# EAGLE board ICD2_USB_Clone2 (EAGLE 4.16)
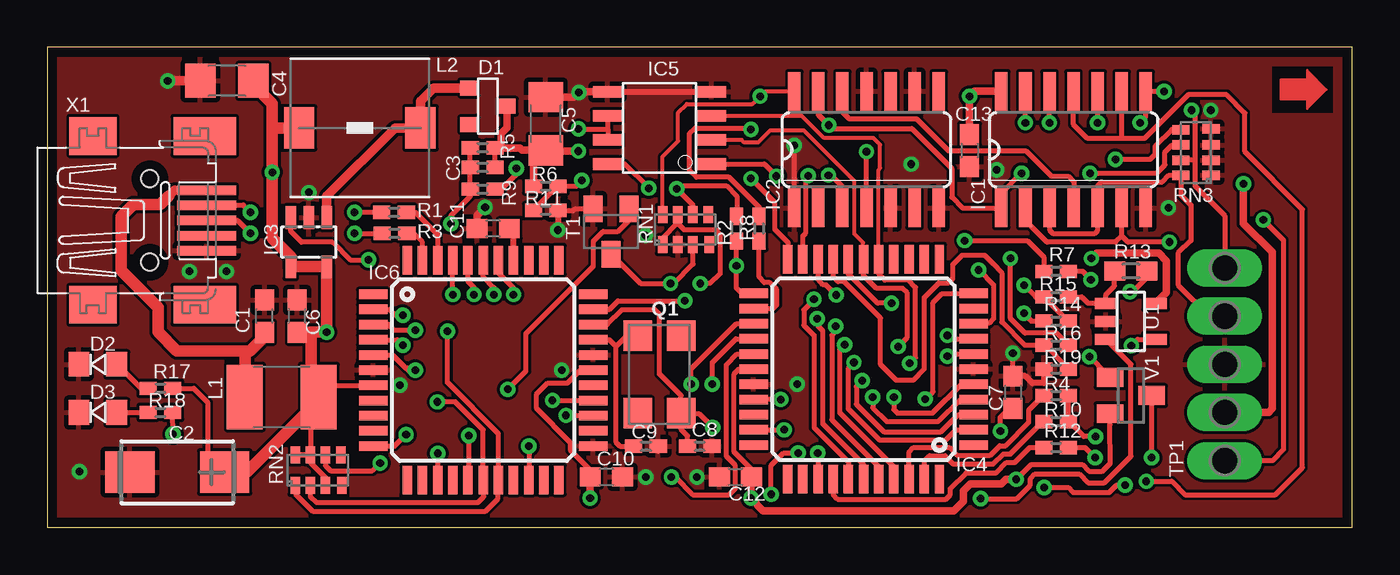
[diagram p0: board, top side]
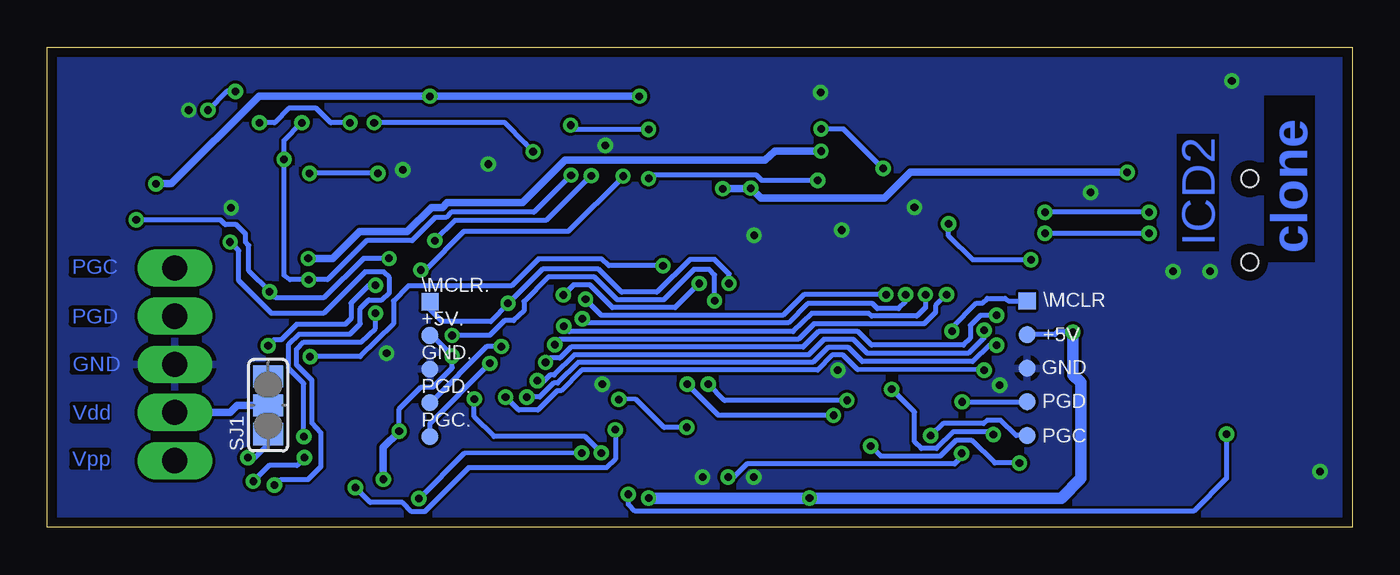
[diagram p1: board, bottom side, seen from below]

Size 68.81 x 25.32 mm. Coordinates in mm from the lower left corner, seen from the top.
Outline: 0,0 68.81,0 68.81,25.32 0,25.32 0,0
Copper layers (1*16): Top 0.035mm / dielectric 1.5mm / Bottom 0.035mm
Design rules "gt_001": minimum track width 6mil, minimum drill 12mil, track to track 6mil, track to pad 6mil, pad to pad 8mil, via to via 8mil, smd to smd 8mil, copper to edge 20mil, drill to drill 8mil, minimum pad ring 10mil, minimum via ring 8mil, stop-mask expansion 4mil, vias tented up to drill 0mil, thermal gap 10mil
tRestrict: area 64.6,21.9 to 67.8,24.3
bRestrict: area 7,14.6 to 9.2,20.7; area 2,14 to 4.6,22.8

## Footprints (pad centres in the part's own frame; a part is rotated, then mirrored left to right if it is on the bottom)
TP09R = smd 0.9 x 0.9: TP 0,0
TP09SQ = smd 0.9 x 0.9: TP 0,0
C0603 = smd 1.1 x 1: 1 -0.85,0; 2 0.85,0
CT6032 = smd 2.6 x 2.2: + 2.5,0; - -2.5,0
C0402 = smd 0.9 x 0.7: 1 -0.65,0; 2 0.65,0
C1206 = smd 1.6 x 1.8: 1 -1.4,0; 2 1.4,0
SOD23 = smd 0.787 x 0.889: 1 -0.94,-0.254; 2 0.991,-0.254; 3 0.025,-2.286
LED0805 = smd 1.1 x 1.3: A -1,0; K 1,0
SO14 = smd 0.66 x 2.032: 1 -3.81,-3.073; 2 -2.54,-3.073; 3 -1.27,-3.073; 4 0,-3.073; 5 1.27,-3.073; 6 2.54,-3.073; 7 3.81,-3.073; 8 3.81,3.073; 9 2.54,3.073; 10 1.27,3.073; 11 0,3.073; 12 -1.27,3.073; 13 -2.54,3.073; 14 -3.81,3.073
SOT23-5 = smd 0.55 x 1.2: 1 -0.95,-1.3; 2 0,-1.3; 3 0.95,-1.3; 4 0.95,1.3; 5 -0.95,1.3
TQFP44 = smd 1.5 x 0.5: 1 -5.8,4; 2 -5.8,3.2; 3 -5.8,2.4; 4 -5.8,1.6; 5 -5.8,0.8; 6 -5.8,0; 7 -5.8,-0.8; 8 -5.8,-1.6; 9 -5.8,-2.4; 10 -5.8,-3.2; 11 -5.8,-4; 23 5.8,-4; 24 5.8,-3.2; 25 5.8,-2.4; 26 5.8,-1.6; 27 5.8,-0.8; 28 5.8,0; 29 5.8,0.8; 30 5.8,1.6; 31 5.8,2.4; 32 5.8,3.2; 33 5.8,4 | smd 0.5 x 1.5: 12 -4,-5.8; 13 -3.2,-5.8; 14 -2.4,-5.8; 15 -1.6,-5.8; 16 -0.8,-5.8; 17 0,-5.8; 18 0.8,-5.8; 19 1.6,-5.8; 20 2.4,-5.8; 21 3.2,-5.8; 22 4,-5.8; 34 4,5.8; 35 3.2,5.8; 36 2.4,5.8; 37 1.6,5.8; 38 0.8,5.8; 39 0,5.8; 40 -0.8,5.8; 41 -1.6,5.8; 42 -2.4,5.8; 43 -3.2,5.8; 44 -4,5.8
SO8 = smd 0.61 x 1.524: 1 -1.27,-2.743; 2 0,-2.743; 3 1.27,-2.743; 4 2.54,-2.743; 5 2.54,2.743; 6 1.27,2.743; 7 0,2.743; 8 -1.27,2.743
L1812 = smd 1.9 x 3.4: 1 -1.95,0; 2 1.95,0
WE-PD_S/M = smd 1.6 x 2.2: 1 -3.2,0; 2 3.2,0
HCX5SB = smd 1.6 x 1.5: 1 -2.05,-1.15; 2 2.05,-1.15; 3 2.05,1.15; 4 -2.05,1.15
R0402 = smd 0.9 x 0.7: 1 -0.65,0; 2 0.65,0
R0603 = smd 1.1 x 1: 1 -0.85,0; 2 0.85,0
CTS-742*083 = smd 0.5 x 0.9: 1 -1.2,-0.8; 2 -0.4,-0.8; 3 0.4,-0.8; 4 1.25,-0.8; 5 1.2,0.8; 6 0.4,0.8; 7 -0.4,0.8; 8 -1.2,0.8
SJ_2 = smd 1.168 x 1.6: 1 -1.524,0; 2 0,0; 3 1.524,0
SC59-BEC = smd 1 x 1.4: B -0.95,-1.2; C 0,1.2; E 0.95,-1.2
P5-25-13 = drill 1.321 pad 1.905 long: 1 -5.08,0; 2 -2.54,0; 3 0,0; 4 2.54,0; 5 5.08,0
SOT23-5' = smd 0.6 x 1.2: 1 -0.95,-1.306; 2 0,-1.306; 3 0.95,-1.306; 4 0.95,1.306; 5 -0.95,1.306
SOT23 = smd 1 x 1.4: 1 -0.95,-1.1; 2 0.95,-1.1; 3 0,1.1
32005-201 = smd 3.1 x 0.5: 1 3,1.6; 2 3,0.8; 3 3,0; 4 3,-0.8; 5 3,-1.6 | smd 2.5 x 2: M1 -3,-4.45; M2 -3,4.45 | smd 3.3 x 2: M3 2.9,4.45; M4 2.9,-4.45 | hole 0.9: 0,2.2; 0,-2.2

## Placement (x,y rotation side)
+5V  TPSQTP09R  [TP09R]  17.14,10.17 270 bottom
+5V.  TPSQTP09R  [TP09R]  48.64,10.12 0 bottom
\MCLR  TPSQTP09SQ  [TP09SQ]  17.14,11.95 270 bottom
\MCLR.  TPSQTP09SQ  [TP09SQ]  48.64,11.9 0 bottom
C1  100n  [C0603]  11.45,11.14 90 top
C2  10u/20V  [CT6032]  6.85,2.91 0 top
C3  220p  [C0402]  22.96,18.99 180 top
C4  1u  [C1206]  9.47,23.56 180 top
C5  4u7/20V  [C1206]  26.28,21.3 90 top
C6  100n  [C0603]  13.18,11.14 90 top
C7  100n  [C0603]  50.92,7.12 270 top
C8  22p  [C0402]  34.41,4.28 0 top
C9  22p  [C0402]  31.57,4.28 0 top
C10  100n  [C0603]  29.48,2.65 180 top
C11  220n  [C0603]  23.52,15.76 180 top
C12  100n  [C0603]  36.29,2.65 0 top
C13  100n  [C0603]  48.64,19.88 270 top
D1  BAT54C  [SOD23]  21.97,22.19 90 top
D2  gn  [LED0805]  2.66,8.6 180 top
D3  rt  [LED0805]  2.66,6.06 180 top
GND  TPSQTP09R  [TP09R]  17.14,8.39 270 bottom
GND.  TPSQTP09R  [TP09R]  48.64,8.34 0 bottom
IC1  74HC126D  [SO14]  54.12,19.93 0 top
IC2  74HC14D  [SO14]  43.2,19.93 0 top
IC3  LM2704  [SOT23-5]  13.79,15.05 180 top
IC4  PIC16F877A-20/PT  [TQFP44]  43.05,8.34 180 top
IC5  MCP41010  [SO8]  32.28,20.43 90 top
IC6  PIC18F4550-I/PT  [TQFP44]  22.98,8.29 0 top
L1  10uH  [L1812]  12.36,6.87 180 top
L2  10uH  [WE-PD_S/M]  16.48,21.07 180 top
PGC  TPSQTP09R  [TP09R]  17.14,4.84 270 bottom
PGC.  TPSQTP09R  [TP09R]  48.64,4.79 0 bottom
PGD  TPSQTP09R  [TP09R]  17.14,6.62 270 bottom
PGD.  TPSQTP09R  [TP09R]  48.64,6.57 0 bottom
Q1  20.00MHz  [HCX5SB]  32.28,8.06 90 top
R1  27R  [R0402]  18.28,16.62 0 top
R2  10k  [R0402]  36.34,15.76 90 top
R3  27R  [R0402]  18.31,15.51 0 top
R4  330R  [R0402]  53.21,6.95 0 top
R5  100k  [R0402]  22.96,20.03 0 top
R6  15k  [R0402]  26.28,18 180 top
R7  1k  [R0402]  53.21,13.5 0 top
R8  1k  [R0402]  37.54,15.76 90 top
R9  4k7  [R0402]  22.96,17.84 180 top
R10  330R  [R0402]  53.21,5.58 0 top
R11  4k7  [R0402]  26.28,16.73 180 top
R12  330R  [R0402]  53.21,4.2 0 top
R13  56R  [R0603]  57.14,13.53 0 top
R14  4k70  [R0402]  53.21,10.88 0 top
R15  13k0  [R0402]  53.21,12.15 180 top
R16  15k  [R0402]  53.21,9.61 0 top
R17  510R  [R0402]  5.96,7.33 0 top
R18  510R  [R0402]  5.96,6.06 0 top
R19  4k7  [R0402]  53.21,8.34 0 top
RN1  10k  [CTS-742*083]  33.65,15.71 0 top
RN2  10k  [CTS-742*083]  14.27,3.01 0 top
RN3  10k  [CTS-742*083]  60.57,19.77 90 top
SJ1  [SJ_2]  57.17,6.44 90 bottom
T1  RN1402  [SC59-BEC]  29.74,15.61 180 top
TP1  TP5P5-25-13  [P5-25-13]  62.1,8.6 90 top
U1  LM7301  [SOT23-5']  57.14,10.86 270 top
U$1  [ARROW]  66.7,23.1 0 top
V1  BSS84  [SOT23]  57.14,6.95 270 top
X1  MINI-USB-SCHIELD-32005-201  [32005-201]  5.41,16.19 0 top

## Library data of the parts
+5V +5V. \MCLR \MCLR. GND GND. PGC PGC. PGD PGD. TP1 = testpad
C1-C13 L1 R1-R19 RN1-RN3 = rcl
D1 = CONTR@3
D2 D3 = CONTR1
IC1 IC2 = 74xx-eu
IC3 = national
IC4 IC6 = microchip
IC5 = MICROCH
L2 = wuerth-elektronik
Q1 = crystal
SJ1 = jumper
T1 = transistor
U1 = linear
U$1 = special_las
V1 = transistor-fet
X1 = con-cypressindustries

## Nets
+5V: +5V..TP +5V.TP C2.+ C4.1 C6.1 C7.2 C10.2 C12.2 IC3.4 IC3.5 IC4.7 IC4.28 IC5.8 IC6.7 IC6.28 L1.1 L2.2 R2.2 R17.2 RN1.6 RN2.3 RN2.7 RN2.8 V1.2
+5V_EXT: SJ1.3
+15V: C3.1 C5.1 D1.3 R5.2 R6.2 U1.5
\CS: IC4.9 IC5.1
ACT: IC4.11 R18.2
BUSY: IC4.8 IC6.32
CS: IC4.27 IC6.14
GND: C1.2 C2.- C4.2 C5.2 C6.2 C7.1 C8.2 C9.2 C10.1 C11.2 C12.1 C13.2 D2.K D3.K GND..TP GND.TP IC1.7 IC2.1 IC2.5 IC2.7 IC2.9 IC2.11 IC3.2 IC4.6 IC4.29 IC5.4 IC5.5 IC6.6 IC6.23 IC6.29 R11.1 R19.1 RN1.2 RN3.1 RN3.2 RN3.3 RN3.4 T1.E TP1.3 U1.2 X1.5
N$1: C1.1 L1.2 X1.1
N$2: C11.1 IC6.37
N$3: D1.2 IC3.1 L2.1
N$4: C9.1 IC6.30 Q1.3
N$5: C3.2 IC3.3 R5.1 R9.2
N$6: C8.1 IC4.30 IC6.31 Q1.1
N$7: IC5.6 IC5.7 R9.1
N$8: IC1.2 IC1.6 R4.2 R10.2
N$9: IC6.16 PGC.TP
N$10: IC6.17 PGD.TP RN2.2
N$11: \MCLR.TP IC6.18 RN2.1
N$12: D2.A R17.1
N$13: R3.1 X1.3
N$14: R1.1 X1.2
N$15: IC1.1 IC2.13 R8.2 RN3.6
N$16: IC4.23 R2.1 V1.1
N$17: IC1.4 IC2.12
N$18: \MCLR..TP IC4.18 RN1.3 T1.C
N$19: IC6.20 RN2.6
N$20: D3.A R18.1
N$21: IC4.22 R6.1 R11.2
N$22: IC1.9 IC1.11 R12.2
N$23: IC1.3 IC1.5 RN3.8 TP1.4
N$26: IC6.11 T1.B
N$27: IC4.20 RN1.1 RN1.7
N$28: R13.1 R15.1 U1.1
N$29: IC4.37 R12.1
N$30: IC1.8 IC1.12 RN3.7 TP1.5
N$32: IC4.42 R4.1
N$33: IC4.43 R10.1
N$34: IC4.19 R16.1 R19.2
N$35: R13.2 R16.2 TP1.1
N$36: R14.2 R15.2 U1.4
N$37: SJ1.1 V1.3
N$39: IC4.36 U1.3
N$40: IC4.32 R14.1
N$41: IC1.13 IC2.4
N$42: IC1.10 IC2.3 R7.2 RN3.5
N$43: IC4.24 R8.1
N$45: IC4.21 R7.1
PD.0: IC4.38 IC6.38
PD.1: IC4.39 IC6.39
PD.2: IC4.40 IC6.40
PD.3: IC4.41 IC6.41
PD.4: IC4.2 IC6.2
PD.5: IC4.3 IC6.3
PD.6: IC4.4 IC6.4
PD.7: IC4.5 IC6.5
RD: IC4.25 IC6.26
SCK: IC4.17 IC5.2 PGD..TP
SI: IC4.16 IC5.3 PGC..TP
T_VDD: C13.1 IC1.14 IC2.14 RN1.8 SJ1.2 TP1.2
USB_+IN: IC6.43 R3.2
USB_-IN: IC6.42 R1.2
WR: IC4.26 IC6.25

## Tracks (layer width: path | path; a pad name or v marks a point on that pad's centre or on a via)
+5V  (via drill 0.4)
  Top 0.152: IC3.4 12.85,13.75
  Top 0.254: RN2.8 13.49,3.81 | IC4.28 36.47,8.34 36.21,8.09 36.21,3.98 37.1,3.09 | C12.2 37.13,2.65 37.13,3.06 37.1,3.09 | IC5.8 30.45,19.16 v31.72,17.89 | R2.2 36.34,16.4 36.37,16.37 36.37,17.46 35.81,18.02 33.34,18.02 v33.19,17.87 34.05,17.01 34.03,17.01 34.05,16.99 RN1.6 | C10.2 28.63,2.71 28.62,2.73 28.62,3.01 | 37.1,2.27 37.1,3.09 | v51.1,2.53 51.89,3.31 54.58,3.31 54.93,2.96 55.65,2.96 56.05,3.37 56.04,5.41 V1.2 | IC6.28 28.11,8.29 27.43,7.61 26.39,7.61 25.8,7.05 25.8,6.26 27.61,4.46 27.61,4.05 28.65,3.01 28.62,3.01 | 28.62,2.5 28.62,3.01 | 28.62,2.43 28.62,3.01 | 28.62,3.01 28.62,3.04 | RN2.7 RN2.8 | RN2.7 13.55,3.81 | IC4.7 47.58,9.14 v47.47,9.03 | C7.2 50.73,6.27 50.26,5.8 v50.26,5.07 | R17.2 7.72,7.33 8.45,6.59 8.45,3.7 9.34,2.91 | 13,3.85 13.05,3.81 RN2.8 | RN2.7 13.87,3.41 13.89,3.39 | RN2.3 14.67,2.35 14.68,2.35 14.68,2.6 13.89,3.39 | 13.9,6.3 13.9,6.31 13.89,6.31 13.89,3.39 | 13.91,7.56 13.99,7.51 14,7.49 IC6.7
  Top 0.406: 37.1,2.27 v37.1,1.54 37.74,0.88 47.82,0.88 48.31,1.36 48.31,1.92 48.69,2.3 50.31,2.3 50.54,2.53 v51.1,2.53 | 28.62,2.5 28.62,2.43 v28.62,1.54
  Top 0.61: C2.+ 9.34,2.91 10.51,2.91 13.9,6.3 13.94,6.39 13.94,6.87 L1.1 13.91,7.56 13.91,10.29 | v14.73,10.3 13.91,10.27 | C6.1 13.9,10.29 13.91,10.29 | 13.91,10.29 v14.73,10.3 | IC3.5 | IC3.5 12.85,13.75 12.85,14.26 11.86,15.25 v11.86,18.73 11.86,21.07 | v14.73,10.3 IC3.5 | 11.86,21.07 L2.2 | C4.1 10.87,23.35 11.86,22.36 11.86,21.07
  Bottom 0.254: v31.72,17.89 31.75,17.87 | v14.73,10.3 15.54,10.3 15.67,10.17 +5V.TP | +5V..TP 48.53,10.12 47.47,9.06 v47.47,9.03 47.44,9.03 47.47,9 47.47,8.42 48.48,7.4 49.09,7.4 50.26,6.24 v50.26,5.07
  Bottom 0.406: 31.75,17.87 v33.19,17.87 | v11.86,18.73 23.29,18.73 24.66,17.36 31.19,17.36 v31.72,17.89 | v50.26,5.07 50.26,5.04 51.1,4.2 v51.1,2.53
  Bottom 0.61: v14.73,10.3 14.73,8.04 14.29,7.63 14.29,2.58 15.34,1.54 v28.62,1.54 v37.1,1.54
+15V  (via drill 0.4)
  Top 0.254: C3.1 R5.2 23.62,20.03
  Top 0.305: 23.62,20.03 23.92,20.03 | 26.26,19.85 C5.1 | 23.97,20 23.97,20.03 23.62,20.03 | 23.62,20.03 R5.2
  Top 0.406: D1.3 24.25,21.09 23.92,20.76 23.92,20.03 | R6.2 25.63,19.23 26.26,19.85 | C5.1 25.04,19.9 24.94,20 23.97,20 | C5.1 27.28,19.85 v28.01,19.85 | v55.06,14.19 55.34,14.47 58.62,14.47 59.02,14.06 59.02,12.38 58.44,11.8 58.44,11.81 U1.5
  Bottom 0.406: v28.01,19.85 30.45,19.85 30.96,19.37 41.52,19.37 43.76,17.13 47.72,17.13 47.98,16.88 48.56,16.88 49.83,15.61 52.34,15.61 53.77,14.19 v55.06,14.19
\CS  (via drill 0.4)
  Top 0.254: IC5.1 37.82,19.16 v38.45,18.53 | v49.12,13.58 49.91,12.79 49.91,11.01 49.65,10.76 48.91,10.76 48.89,10.74 IC4.9
  Bottom 0.254: v38.45,18.53 38.45,18.48 41.35,15.61 46.86,15.61 48.86,13.58 v49.12,13.58
ACT  (via drill 0.4)
  Top 0.254: v38.17,1.74 38.17,3.26 38.83,3.92 v39.59,3.92 | v46.3,6.77 46.71,7.15 46.71,11.85 47.19,12.33 48.81,12.33 48.81,12.34 IC4.11 | v6.62,4.92 R18.2
  Bottom 0.254: v6.62,4.92 6.62,2.58 8.35,0.85 37.82,0.85 38.17,1.21 v38.17,1.74 | v39.59,3.92 40.46,4.79 45.26,4.79 46.3,5.83 v46.3,6.77
BUSY  (via drill 0.4)
  Top 0.254: IC6.32 29.59,11.49 29.64,11.49 30.09,11.95 v33.62,11.95 | 48.81,9.94 | 48.81,9.94 IC4.8 | v47.47,10.12 47.64,9.94 48.81,9.94
  Bottom 0.254: v47.47,10.12 45.49,10.12 44.7,10.91 44.22,10.91 43.68,11.42 43.68,11.93 42.41,13.2 39.95,13.2 38.75,12 36.32,12 34.72,13.6 33.9,13.6 33.62,13.32 v33.62,11.95
CS  (via drill 0.4)
  Top 0.254: IC4.27 36.38,9.14 35.81,8.57 35.81,3.75 36.29,3.26 36.29,2.04 35.96,1.71 34.03,1.71 33.09,2.65 v32.91,2.65 | IC6.14 20.58,2.55 20.59,2.55 v20.59,3.9
  Bottom 0.254: v32.91,2.65 32.61,2.65 31.92,3.34 20.98,3.34 20.59,3.72 v20.59,3.9
GND  (via drill 0.4)
  Top 0.152: C1.2 11.48,12 C1.2
  Top 0.254: T1.E 27.84,16.81 27.73,16.7 26.93,16.7 | 26.93,16.7 26.92,16.7 | R11.1 26.93,16.7 | IC2.1 v39.39,20.16 | RN3.2 61.37,19.42 61.36,19.42 61.37,19.41 | RN3.4 61.37,21.04 61.39,21.07 61.37,21.06 | C10.1 30.32,2.65 | IC6.23 28.78,4.2 | v39.54,7.56 39.53,7.54 | 50.95,7.96 50.95,7.97 C7.1 | C7.1 v50.92,9.18 | C7.1 50.92,7.96 | C9.2 32.22,4.25 32.23,4.25 32.23,4 | RN3.3 61.39,20.21 61.37,20.19 RN3.3
  Top 0.305: R11.1 26.93,15.7 v26.92,15.68 | IC5.5 29.54,23 29.56,22.95 29.59,22.97 IC5.4 | 50.95,7.97 51.57,7.97 51.94,7.61 52.55,7.61 52.55,8.22 52.57,8.24 52.56,8.27 R19.1
  Top 0.406: C11.2 22.67,16.46 v23.08,16.88 | C5.2 27.79,22.7 v28.04,22.95 28.06,22.97 IC5.5 | D3.K
  Top 0.508: v6.34,23.56 C4.2
  Top 0.61: C1.2
  other vias: 13.79,17.67 18.59,7.51 1.7,2.93 9.44,13.5 45.56,19.16 50.06,18.86 31.54,15.41 61.36,22.01 59.13,16.85 31.57,2.65 34.26,2.65 27.12,8.29 7.49,13.5
  pour Bottom: 0.25,25.08 68.58,25.08 68.58,0.24 0.2,0.24 0.2,25.03
  pour Top: 0.25,25.01 68.58,25.01 68.58,0.29 0.25,0.29
N$1
  Top 0.406: X1.1 | X1.1 | 6.7,17.79 X1.1 | X1.1
  Top 0.508: 6.4,17.49 6.7,17.79
  Top 0.61: 6.4,17.49 5.94,17.03 4.52,17.03 3.88,16.4 3.88,13.55 5.84,11.6 5.84,10.3 6.83,9.31 10.43,9.31 | C1.1 11.45,10.07 10.69,9.31 10.43,9.31 | L1.2 10.44,9.3 10.43,9.31
N$2
  Top 0.305: C11.1 24.37,15.66 24.35,15.66 24.58,15.43 IC6.37
N$3
  Top 0.508: IC3.1 14.74,17.47 18.33,21.07 L2.1 | L2.1 | L2.1 19.68,21.04 19.68,22.49 20.37,23.18 D1.2
N$4
  Top 0.254: IC6.30 29.64,9.89 29.99,9.54 | 29.99,9.54 30.73,10.27 31.09,10.27 Q1.3 | 29.99,9.54 29.99,4.48 30.2,4.28 C9.1
N$5  (via drill 0.4)
  Top 0.152: C3.2 22.32,18.99
  Top 0.254: 22.31,19 R5.1 | 22.31,19 C3.2 | 22.31,19 C3.2 R9.2 22.3,17.64 22.3,17.46 21.28,16.45 v21.28,16.01 | IC3.3 12.84,15.62 13.41,15.05 15.03,15.05 15.97,14.11 v16.94,14.11
  Bottom 0.254: v16.94,14.11 20.01,14.11 21.28,15.38 v21.28,16.01
N$6  (via drill 0.4)
  Top 0.254: IC4.30 v38.68,6.74 | IC6.31 29.52,10.69 30.3,11.47 32.05,11.47 32.28,11.24 32.28,8.09 33.42,6.95 Q1.1 | C8.1 33.76,4.83 33.42,5.17 Q1.1 | Q1.1 33.43,5.98 Q1.1 | Q1.1 34.36,6.01 v35.1,5.27
  Bottom 0.254: v35.1,5.27 36.29,5.27 37.77,6.74 38.65,6.77 v38.68,6.74
N$7  (via drill 0.4)
  Top 0.254: v28.01,21.02 29.56,21.02 | IC5.6 29.54,21.73 29.56,21.68 29.56,21.02 | IC5.7 29.56,20.46 29.56,21.02 | R9.1 23.95,17.84 24.73,18.63 v24.73,18.94
  Bottom 0.254: v24.73,18.94 26.82,21.02 v28.01,21.02
N$8  (via drill 0.4)
  Top 0.254: IC1.2 51.58,16.19 52.72,15.05 56.33,15.05 56.66,15.38 | 56.66,15.38 IC1.6 | R4.2 53.86,6.92 53.87,6.92 53.86,6.91 R10.2 | R10.2 | 56.66,15.38 56.99,15.05 v59.18,15.05 | R10.2 54.66,4.79 v55.29,4.79
  Bottom 0.254: v59.18,15.05 58.72,14.59 58.72,13.02 56.99,11.29 54.25,11.29 52.06,13.47 51.07,13.47 50.77,13.17 50.77,12.38 51.18,12 51.86,12 52.32,11.54 52.32,10.73 52.85,10.2 55.54,10.2 56.08,9.66 56.08,8.37 55.29,7.58 v55.29,4.79
N$9  (via drill 0.4)
  Top 0.254: IC6.16 22.18,2.48 22.2,2.48 22.22,2.5 v22.22,4.84
  Bottom 0.254: PGC.TP 17.72,4.84 18.54,5.65 19.25,5.65 19.43,5.47 21.56,5.47 v22.22,4.84
N$10  (via drill 0.4)
  Top 0.254: RN2.2 13.87,1.63 14.19,1.31 22.7,1.31 23.01,1.61 23.01,2.49 IC6.17 22.98,5.14 21.51,6.62 v20.57,6.62
  Bottom 0.254: v20.57,6.62 PGD.TP
N$11  (via drill 0.4)
  Top 0.254: RN2.1 13.07,1.77 13.99,0.85 23.11,0.85 23.77,1.51 23.77,2.48 23.78,2.48 IC6.18 23.78,2.55 23.8,2.58 23.8,4.94 21.1,7.63 v21.1,10.35
  Bottom 0.254: \MCLR.TP 18.13,11.95 18.31,12.08 19.25,12.08 19.5,11.82 19.81,11.82 21.1,10.53 v21.1,10.35
N$12
  Top 0.254: D2.A 3.66,8.62 3.65,8.62 4.95,7.33 R17.1
N$13  (via drill 0.4)
  Top 0.254: v16.2,15.51 R3.1 | v10.71,15.51 10.03,16.19 X1.3
  Bottom 0.254: v10.71,15.51 v16.2,15.51
N$14  (via drill 0.4)
  Top 0.152: X1.2 8.43,17.01 8.43,16.99
  Top 0.254: v16.2,16.62 R1.1 | X1.2 8.43,16.99 9.16,17.01 10.33,17.01 v10.71,16.62
  Bottom 0.254: v10.71,16.62 v16.2,16.62
N$15  (via drill 0.4)
  Top 0.254: 40.66,21.76 IC2.13 | 40.66,21.76 41.37,21.04 45.59,21.04 47.7,18.94 47.7,17.41 48.25,16.85 IC1.1 50.31,17.62 v51.38,18.68 | R8.2 37.54,16.9 35.96,18.48 34.23,18.48 33.88,18.83 33.88,20.79 34.16,21.07 37.03,21.07 v37.1,20.99 | 40.66,21.76 40.69,21.76 v41.22,21.22 | RN3.6 59.76,20.16 59.3,20.16 58.95,19.8 58.95,19.11 58.52,18.68 v54.99,18.68
  Bottom 0.254: v37.1,20.99 40.99,20.99 v41.22,21.22 | v51.38,18.68 v54.99,18.68
N$16  (via drill 0.4)
  Top 0.254: R2.1 v36.34,13.81 36.34,12.64 36.65,12.33 37.25,12.33 | 37.25,12.33 37.26,12.33 | IC4.23 37.25,12.33 | V1.1 55.85,8.09 v54.96,9
  Bottom 0.254: v36.34,13.81 39.21,13.81 39.59,14.16 42.92,14.16 44.34,12.74 49.78,12.74 50.57,11.95 50.57,10.73 52.32,9 v54.96,9
N$17
  Top 0.254: IC2.12 41.93,21.91 42.29,21.55 45.84,21.55 47.52,19.88 51.61,19.88 52.95,18.53 53.84,18.53 54.15,18.22 54.15,16.9 54.12,16.9 IC1.4
N$18  (via drill 0.4)
  Top 0.152: 34.06,14.92 RN1.3 | 30.31,13.84 30.22,13.75 T1.C
  Top 0.254: T1.C 30.31,13.84 31.29,12.87 v32.86,12.87 33.04,12.87 34.06,13.88 34.06,14.92 34.05,14.95 | IC4.18 42.25,13.36 43.78,11.82 v44.52,11.82
  Bottom 0.254: v32.86,12.87 32.86,13.37 33.62,14.14 34.92,14.14 36.67,12.41 38.53,12.41 39.75,13.63 42.69,13.63 44.51,11.81 | 44.51,11.81 45.44,10.86 48,10.86 48.64,11.49 \MCLR..TP | v44.52,11.82 44.51,11.82 44.51,11.81
N$19  (via drill 0.4)
  Top 0.254: RN2.6 14.67,3.25 14.93,2.98 17.14,2.98 v17.55,3.39 | IC6.20 25.39,2.53 v25.39,4.28
  Bottom 0.254: v17.55,3.39 18.84,3.39 20.06,4.58 20.9,4.58 21.74,3.75 24.86,3.75 v25.39,4.28
N$20
  Top 0.254: D3.A R18.1
N$21  (via drill 0.4)
  Top 0.254: R11.2 26.87,17.97 26.92,18 R6.1 27.88,18 v28.19,18.3 | v37.1,18.4 38.35,17.16 38.35,15.74 39.06,15.02 39.06,14.21 39.05,14.21 IC4.22
  Bottom 0.254: v28.19,18.3 31.14,18.3 31.42,18.58 36.93,18.58 v37.1,18.4
N$22  (via drill 0.4)
  Top 0.254: 54.12,22.97 IC1.11 54.12,21.25 54.86,20.51 56.66,20.51 | v57.96,2.43 59.3,2.43 59.99,1.71 64.77,1.71 66.19,3.14 66.19,16.78 63.16,19.82 63.16,21.86 62.2,22.82 60.17,22.82 57.86,20.51 56.66,20.51 | R12.2 54.73,4.2 v55.27,3.67 | 56.66,20.51 IC1.9
  Bottom 0.254: v55.27,3.67 55.62,3.29 55.65,3.26 57.12,3.26 v57.96,2.43
N$23
  Top 0.254: IC1.3 52.85,15.68 53.03,15.51 55.24,15.51 55.39,15.66 IC1.5 55.39,18.02 55.6,18.22 58.8,18.22 59.15,18.58 59.76,18.58 59.76,18.57 RN3.8 59.77,17.53 60.32,17.01 60.32,15.13 59.63,14.47 59.63,12.79 61.28,11.14 TP1.4
N$26  (via drill 0.4)
  Top 0.254: IC6.11 18.32,4.29 v18.92,4.89 | v24.28,7.28 25.24,8.24 25.24,10.22 28.8,13.78 28.8,15.1 29.31,15.61 30.09,15.61 30.68,16.19 T1.B
  Bottom 0.254: v18.92,4.89 19.07,5.04 21.03,5.04 21.92,4.15 22.73,4.15 23.08,4.51 23.08,6.08 v24.28,7.28
N$27  (via drill 0.4)
  Top 0.203: 33.24,16.47 33.25,16.47 RN1.7 | 40.66,14.16 40.65,14.16 IC4.20
  Top 0.254: RN1.1 32.45,15.25 33.24,16.04 | 33.24,16.04 33.24,16.47 | 33.24,16.04 33.57,15.71 35.22,15.71 | 40.66,14.16 40.66,13.07 40.91,12.79 41.07,12.79 v41.6,12.26 | 35.22,15.71 35.25,15.71 | v34.44,12.87 34.95,12.87 35.48,13.37 35.48,15.46 35.22,15.71
  Bottom 0.254: v41.6,12.26 41.07,12.79 40.2,12.79 39.01,11.6 35.71,11.6 v34.44,12.87
N$28
  Top 0.254: R15.1 54.55,12.15 54.88,11.82 55.77,11.82 55.8,11.85 U1.1 55.84,12.3 56.28,12.74 56.28,13.47 56.29,13.5 R13.1
N$29
  Top 0.254: IC4.37 41.45,1.71 41.68,1.49 47.39,1.49 47.62,1.71 47.62,2.04 48.46,2.88 50.06,2.88 50.59,3.42 51.02,3.42 51.81,4.2 R12.1 52.56,4.18 52.55,4.18
N$30  (via drill 0.4)
  Top 0.254: TP1.5 62.1,16.45 60.52,18.02 60.52,19.22 60.52,19.37 | 60.52,19.37 RN3.7 | 60.52,19.37 | v52.85,21.35 IC1.12 | v57.63,21.35 57.93,21.65 IC1.8 v58.9,23 | v60.34,22.01 60.52,21.83 60.52,19.37 | 60.52,19.37
  Bottom 0.254: v52.85,21.35 53.87,21.35 54.63,22.11 56.08,22.11 56.84,21.35 v57.63,21.35 | v58.9,23 59.35,23 v60.34,22.01
N$32
  Top 0.254: IC4.42 45.45,3.96 45.69,4.2 47.57,4.2 47.98,3.8 49.73,3.8 50.24,4.31 50.54,4.31 51.76,5.52 51.76,6.19 52.55,6.97 52.56,6.97 R4.1
N$33
  Top 0.254: IC4.43 46.25,3.49 46.53,3.77 47.34,3.77 47.77,3.34 49.88,3.34 50.41,3.87 50.79,3.87 52.5,5.58 R10.1
N$34
  Top 0.254: R19.2 52.57,9.64 R16.1 51.53,9.61 50.34,10.83 50.34,13.42 49.88,13.91 49.42,14.36 48.25,14.36 47.75,13.86 47.75,13.12 47.52,12.89 47.01,12.89 46.25,12.13 46.25,8.34 45.66,7.76 44.77,7.76 43.94,8.6 43.94,11.04 42.01,12.97 41.7,12.97 41.45,13.22 IC4.19
N$35  (via drill 0.4)
  Top 0.254: R13.2 57.99,13.18 57.25,12.43 v57.09,12.43 | R16.2 53.23,10.25 51.56,10.25 50.79,11.01 v50.79,14.19 | TP1.1 64.61,3.52 65.2,4.1 65.2,15.15 v64.13,16.22
  Bottom 0.254: v50.79,14.19 52.14,14.19 54.25,12.1 56.76,12.1 v57.09,12.43 58.19,13.53 58.19,14.87 58.36,15.05 58.36,15.48 58.85,15.96 59.43,15.96 59.68,16.22 v64.13,16.22
N$36  (via drill 0.4)
  Top 0.254: R14.2 53.82,10.88 R15.2 52.56,12.14 52.13,12.14 v51.51,12.76 | v57.17,9.59 57.5,9.92 58.44,9.92 58.44,9.91 U1.4
  Bottom 0.254: v51.51,12.76 51.86,12.76 52.8,11.82 52.8,11.01 53.11,10.71 55.67,10.71 56.48,9.89 56.87,9.89 v57.17,9.59
N$37  (via drill 0.4)
  Top 0.254: V1.3 58.24,3.81 v58.24,3.67
  Bottom 0.254: SJ1.1 57.17,4.38 57.88,3.67 v58.24,3.67
N$39  (via drill 0.4)
  Top 0.254: v49.22,1.51 51.12,1.51 51.84,2.22 51.84,2.55 52.09,2.81 54.43,2.81 54.88,2.35 55.75,2.35 57.14,3.75 57.14,8.6 U1.3 | 40.66,2.57 40.66,2.55 | IC4.36 40.66,2.57 | v40.63,3.92 40.66,3.92 40.66,2.57
  Bottom 0.254: v40.63,3.92 46.83,3.9 v49.22,1.51
N$40  (via drill 0.4)
  Top 0.254: R14.1 51.89,10.88 v51.51,11.29 | v56.84,2.22 56.38,2.22 56,1.84 54.1,1.84 53.84,2.1 v52.57,2.1 | IC4.32 37.26,5.14 v38.86,5.14
  Bottom 0.254: v51.51,11.29 51.51,10.5 52.27,9.77 55.29,9.77 55.67,9.39 55.67,8.57 54.86,7.76 54.86,5.5 54.38,4.99 54.38,3.21 55.06,2.53 56.51,2.53 v56.84,2.22 | v52.57,2.1 51.79,1.31 50.08,1.31 49.6,0.83 48.91,0.83 46.6,3.14 39.31,3.14 38.86,3.59 v38.86,5.14
N$41  (via drill 0.4)
  Top 0.254: IC2.4 v43.2,19.82 | v51.58,21.35 IC1.13
  Bottom 0.254: v43.2,19.82 43.58,20.26 44.67,21.35 v51.58,21.35
N$42  (via drill 0.4)
  Top 0.254: v55.39,21.35 IC1.10 | RN3.5 59.74,20.97 59.71,20.99 59.3,20.99 58.44,20.13 58.44,19.7 58.16,19.42 v56.33,19.42 | IC2.3 41.93,17.97 41.32,18.58 v41.19,18.58 | v55.04,13.07 54.6,13.5 R7.2
  Bottom 0.254: v41.19,18.58 43.15,16.62 47.52,16.62 47.8,16.35 48.36,16.35 49.58,15.13 51.99,15.13 54.05,13.07 v55.04,13.07 56.03,13.07 56.33,13.3 v56.33,19.42 56.33,20.41 v55.39,21.35
N$43
  Top 0.254: R8.1 37.54,13.22 37.82,12.92 38.09,12.92 38.48,12.54 38.48,11.75 38.27,11.54 37.23,11.54 | 37.23,11.54 | IC4.24 37.23,11.54
N$45  (via drill 0.4)
  Top 0.254: IC4.21 39.85,15.38 40,15.53 40,18.43 v40.13,18.55 | R7.1 52.56,13.47 52.55,14.26 51.68,15.13 v48.38,15.13
  Bottom 0.254: v40.13,18.55 40.15,18.55 42.52,16.19 47.31,16.19 v48.38,15.13
PD.0  (via drill 0.4)
  Top 0.254: IC4.38 42.25,3.45 40.43,5.27 40.43,10.12 39.9,10.66 39.9,11.47 40.44,12.01 40.45,12.01 v40.43,12.03 | v24.58,12.28 24.58,12.64 23.8,13.42 IC6.38
  Bottom 0.254: v24.58,12.28 28.9,12.28 30.02,11.19 39.59,11.19 v40.43,12.03
PD.1  (via drill 0.4)
  Top 0.254: v40.61,11.01 40.61,10.66 40.89,10.38 40.89,5.47 43.05,3.31 IC4.39 | v23.54,12.28 23.54,12.66 22.98,13.22 IC6.39
  Bottom 0.254: v23.54,12.28 23.54,11.93 23.92,11.54 25.04,11.54 25.29,11.8 28.72,11.8 29.74,10.78 40.38,10.78 v40.61,11.01
PD.2  (via drill 0.4)
  Top 0.254: IC4.40 43.85,3.2 41.37,5.68 41.37,10.15 41.57,10.35 v41.57,10.6 | v22.5,12.28 22.5,12.66 22.2,12.97 22.2,14.06 22.18,14.06 IC6.40
  Bottom 0.254: v22.5,12.28 22.5,11.6 22.96,11.14 25.34,11.14 25.5,11.29 28.49,11.29 29.48,10.33 41.29,10.33 v41.57,10.6
PD.3  (via drill 0.4)
  Top 0.254: v42.06,9.64 41.78,9.36 41.78,6.06 44.65,3.19 IC4.41 | 21.38,14.08 | 21.38,14.08 IC6.41 | v21.38,12.28 21.38,14.08
  Bottom 0.254: v21.38,12.28 21.97,11.7 21.97,11.34 22.58,10.73 28.39,10.73 29.21,9.92 41.78,9.92 v42.06,9.64
PD.4  (via drill 0.4)
  Top 0.254: IC6.2 18.05,11.49 18.39,11.19 v18.74,11.19 | v18.74,11.19 | v42.54,8.7 42.23,8.37 42.23,6.26 43.89,4.61 47.39,4.61 47.92,5.14 48.81,5.14 IC4.2
  Bottom 0.254: v18.74,11.19 19.6,11.19 20.14,10.66 20.14,9.97 20.49,9.61 25.34,9.61 26.05,10.33 28.14,10.33 28.95,9.51 41.19,9.51 41.78,8.93 42.31,8.93 v42.54,8.7
PD.5  (via drill 0.4)
  Top 0.254: v42.97,7.73 42.67,7.43 42.67,6.49 44.11,5.04 47.14,5.04 48.05,5.96 IC4.3 | IC6.3 17.98,10.71 18.28,10.4 v19.4,10.4
  Bottom 0.254: v19.4,10.4 19.4,10.02 20.24,9.18 25.57,9.18 26.31,9.92 27.86,9.92 28.67,9.11 41.02,9.11 42.08,8.04 42.31,8.04 42.64,7.71 42.95,7.71 v42.97,7.73
PD.6  (via drill 0.4)
  Top 0.254: IC4.4 48.15,6.74 46.96,5.58 44.39,5.58 44.27,5.58 43.53,6.31 v43.53,6.87 | IC6.4 | IC6.4 | IC6.4 18.46,9.89 v18.74,9.61
  Bottom 0.254: v18.74,9.61 19.1,9.61 20.01,8.75 25.83,8.75 26.56,9.49 27.66,9.49 28.44,8.7 40.81,8.7 41.9,7.61 42.11,7.61 42.84,6.87 v43.53,6.87
PD.7  (via drill 0.4)
  Top 0.152: 18.93,8.38 19.02,8.47 v19.4,8.29
  Top 0.254: IC6.5 18.22,9.09 18.93,8.38 19.02,8.29 19.39,8.28 | IC4.5 48.81,7.53 48.2,7.53 46.68,6.03 44.83,6.03 44.65,6.21 v44.65,6.87
  Bottom 0.254: v19.4,8.29 26.08,8.32 26.84,9.08 27.43,9.08 28.19,8.29 40.63,8.29 41.73,7.2 41.93,7.2 42.95,6.19 43.96,6.19 v44.65,6.87
RD  (via drill 0.4)
  Top 0.254: 28.8,6.69 | 28.8,6.69 IC6.26 | v26.64,6.69 28.8,6.69 | IC4.25 36.35,10.74 33.95,8.34 v33.95,7.56
  Bottom 0.254: v33.95,7.56 33.09,6.69 v26.64,6.69
SCK  (via drill 0.4)
  Top 0.203: IC5.2 36.62,20.43 36.75,20.31 37.48,20.31 38.12,20.94 39.9,20.94 42.56,18.28 42.56,15.48 43.02,15.02 43.02,14.14 IC4.17
  Top 0.254: IC4.17 43.05,13.3 43.73,12.61 45.1,12.61 45.36,12.36 45.36,10.02 v44.88,9.54
  Bottom 0.254: v44.88,9.54 45.64,9.54 48.61,6.57 PGD..TP
SI  (via drill 0.4)
  Top 0.203: IC5.3 39.8,21.7 40.96,20.54 43.56,20.54 43.91,20.18 43.91,18.96 43.84,18.86 43.84,14.06 43.85,14.06 IC4.16
  Top 0.254: v45.49,8.65 45.79,8.95 45.79,12.66 45.41,13.04 44.17,13.04 43.86,13.35 43.86,14.08 43.85,14.11 IC4.16
  Bottom 0.254: PGC..TP 48.64,5.47 v45.49,8.65
T_VDD  (via drill 0.4)
  Top 0.203: RN1.8 32.45,19.56 33.27,20.38 33.27,21.88 33.73,22.34 37.18,22.34 v37.59,22.75 37.84,23 IC2.14
  Top 0.305: 39.42,23.05 39.39,23.05 IC2.14
  Top 0.406: IC1.14 48.89,23 v48.64,22.75 C13.1 | v63.09,18.12 63.09,16.01 64.61,14.52 64.61,6.26 64.41,6.06 TP1.2 62.07,6.06
  Bottom 0.254: TP1.2 62.07,6.08 62.05,6.06
  Bottom 0.406: SJ1.2 58.8,6.44 59.18,6.06 62.05,6.06 | v63.09,18.12 62.28,18.12 57.65,22.75 v48.64,22.75 v37.59,22.75
USB_+IN
  Top 0.254: R3.2 19.32,15.51 19.78,15.05 19.78,14.11 | 19.78,14.11 | IC6.43 19.78,14.11
USB_-IN
  Top 0.254: R1.2 19.4,16.62 20.57,15.46 20.57,14.09 | 20.57,14.09 20.57,14.08 | 20.57,14.09 IC6.42
WR  (via drill 0.4)
  Top 0.254: IC4.26 36.32,9.94 35.07,8.7 v35.07,7.56 | IC6.25 28.75,5.89 28.75,5.91 v27.35,5.91
  Bottom 0.254: v35.07,7.56 33.42,5.91 v27.35,5.91

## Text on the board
Bottom: ICD2 | clone | PGC | PGD | GND | Vdd | Vpp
